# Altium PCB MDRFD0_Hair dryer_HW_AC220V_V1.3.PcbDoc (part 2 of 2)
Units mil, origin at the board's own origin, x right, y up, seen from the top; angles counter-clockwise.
Board outline 2501.37 x 2501.36 mil, 2 copper layers (Top Layer, Bottom Layer), stack 65.792 mil thick; 130 components, 77 nets, 332 pads, 233 vias.
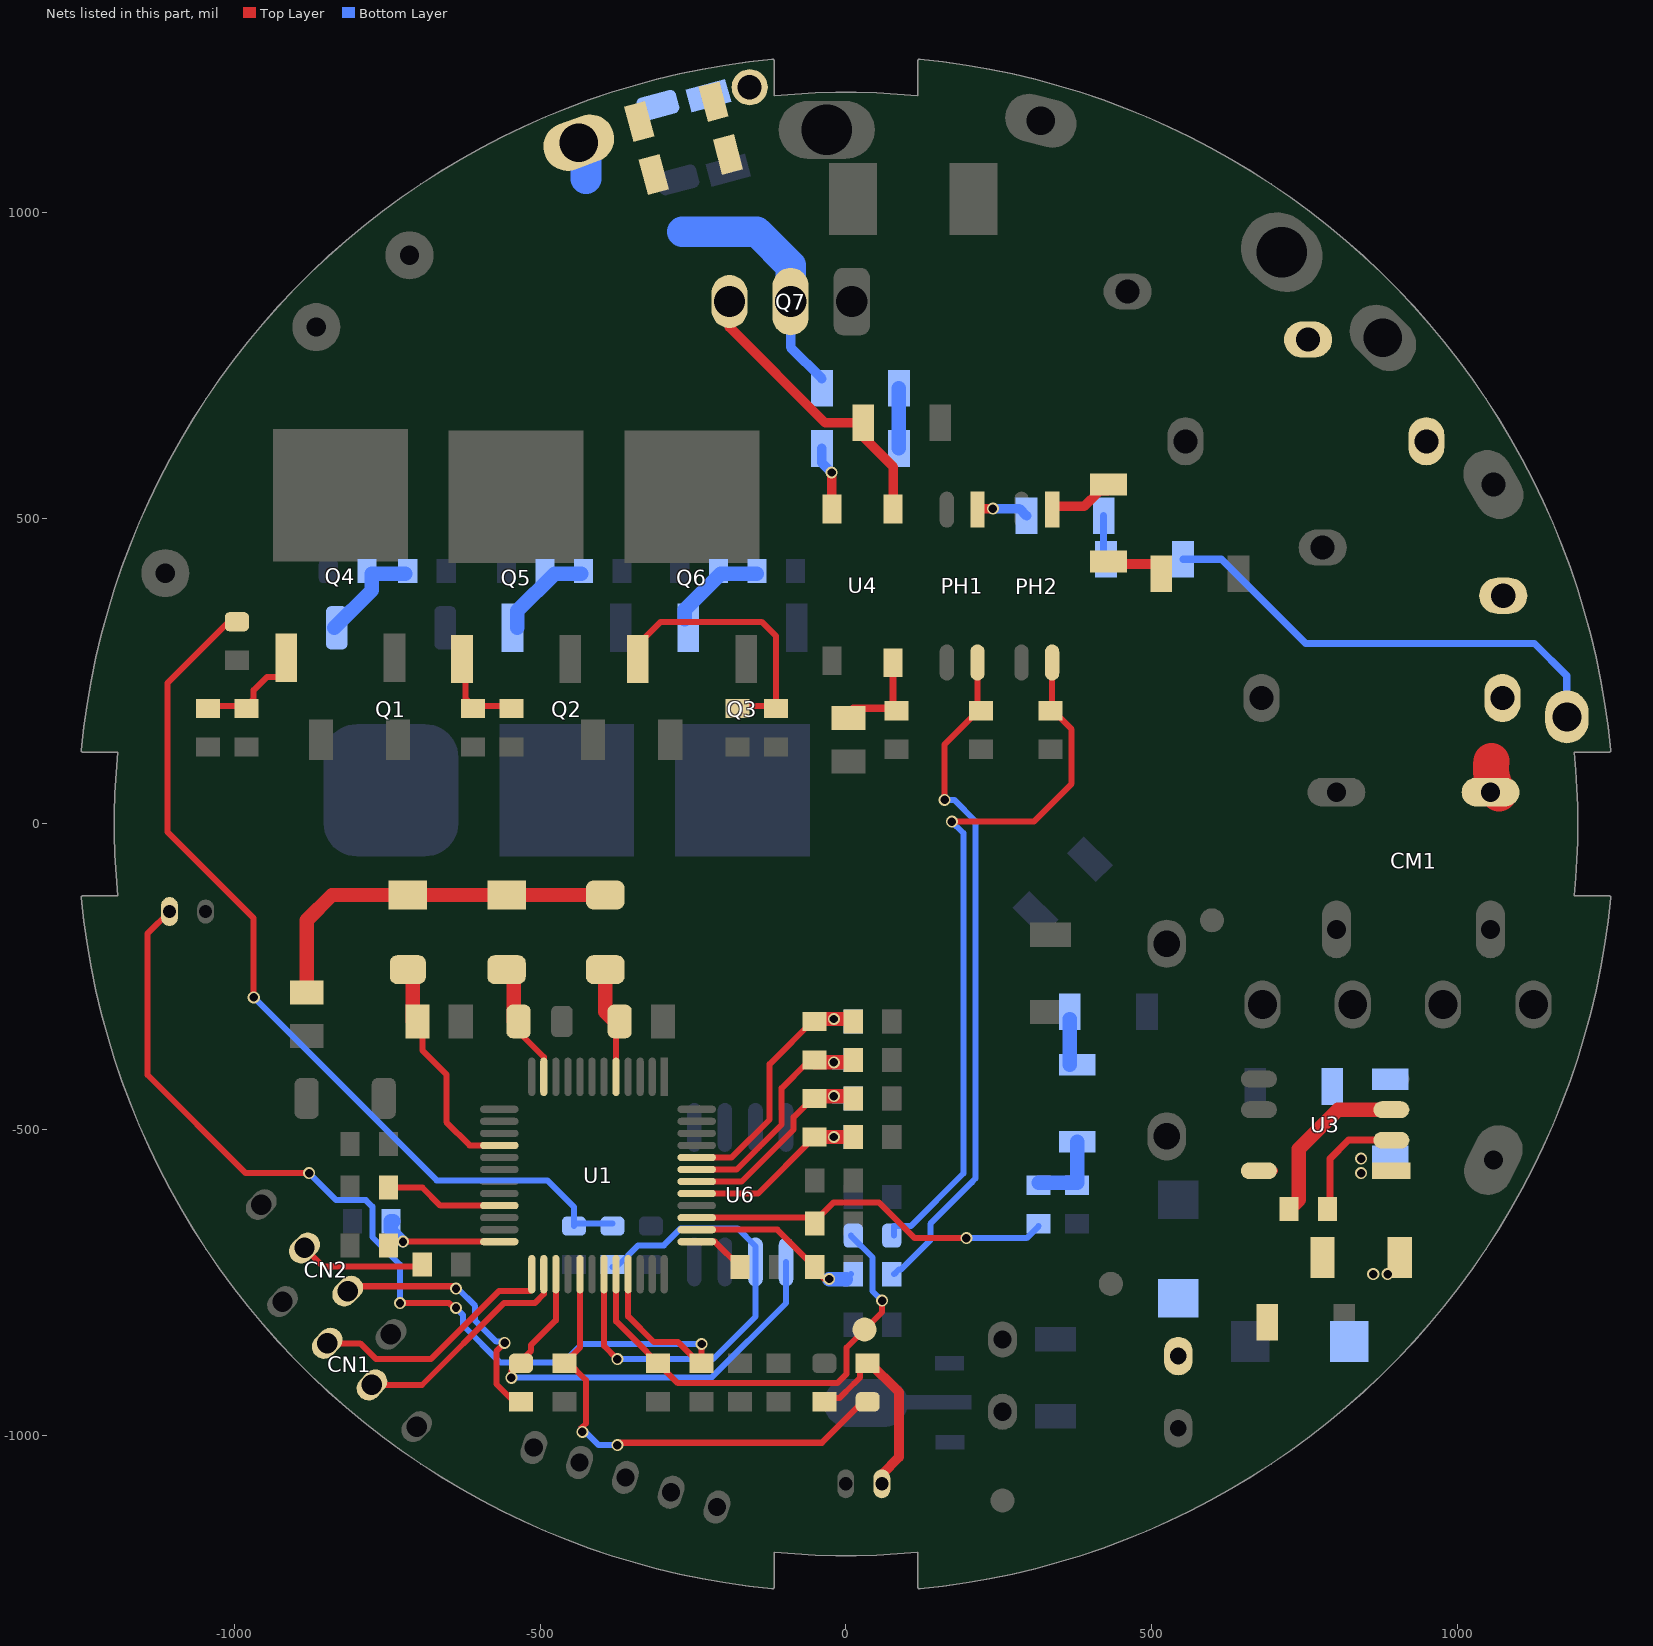
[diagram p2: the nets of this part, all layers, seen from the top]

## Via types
v1: diameter 19.68, hole 13.78, Top Layer to Bottom Layer, tented both sides, 233 vias

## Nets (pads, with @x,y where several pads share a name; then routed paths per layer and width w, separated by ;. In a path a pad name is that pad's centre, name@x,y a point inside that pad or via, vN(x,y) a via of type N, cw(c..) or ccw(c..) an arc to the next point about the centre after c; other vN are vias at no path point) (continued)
NetC5_2: C5.2 C6.1 D4.2 L2.1 R7.1 U3.3 U3.8 | length 306.3
  Top Layer w11.81: U3.8@677.64,-566.93 U3.8@700.79,-566.93
  Top Layer w23.62: C6.1@724.41,-629.92 740.16,-614.17 740.16,-531.5 804.53,-467.13 U3.3@891.73,-467.13
NetC6_2: C6.2 U3.2 | length 201.5
  Top Layer w11.81: C6.2@791.34,-629.92 791.34,-547.24 821.65,-516.93 U3.2@897.64,-516.93
NetC11_1: C11.1 C26.1 pad.2 R41.1 R42.1
NetC29_2: C29.2 R36.1 U1.24 | length 230.7
  Top Layer w9.84: C29.2@-748.03,-688.98 -742.13,-683.07 v1(-724.41,-683.07) U1.24@-566.93,-683.07
  Bottom Layer w19.68: R36.1@-744.09,-663.39 v1(-724.41,-683.07)
  Bottom Layer w23.62: R36.1@-744.09,-663.39 R36.1@-744.09,-653.54 ; R36.1@-744.09,-649.61 R36.1@-744.09,-653.54 ; R36.1@-740.16,-649.61 R36.1@-744.09,-653.54
NetC32_1: C32.1 U1.21 | length 193.3
  Top Layer w9.84: C32.1@-748.03,-594.49 -692.91,-594.49 -663.39,-624.02 U1.21@-566.93,-624.02
NetCM1_1: CM1.1 CX1.2 CX2.2 MOV1.2 THR1.2 | length 111.6
  Top Layer w59.06: 1055.74,103.06 ccw(c1125.8,91.05) 1067.77,50.01 cw(c1125.8,91.05) 1055.74,103.06
NetD5_1: D5.1 D6.1 D7.1 R44.2 | length 615.5
  Top Layer w23.62: R44.2@-881.89,-267.72 -881.89,-157.48 -840.55,-116.14 D7.1@-393.7,-116.14
NetNTC1_2: NTC1.2 R43.2 R46.1 | length 1488.7
  Top Layer w9.84: NTC1.2@-996.06,334.65 -1005.44,334.65 -1109.25,230.83 -1109.25,-13.31 -968.5,-154.06 v1(-968.5,-283.46)
  Bottom Layer w9.84: v1(-968.5,-283.46) -669.29,-582.68 -488.38,-582.68 -444.88,-626.18 R43.2@-444.88,-653.54 ; R43.2@-444.88,-657.48 R43.2@-444.88,-653.54 ; R46.1@-381.89,-653.54 R43.2@-444.88,-653.54
NetNTC_1: NTC.1 R30.1 R40.1 | length 330.2
  Top Layer w9.84: R40.1@-35.43,-948.82 -25.59,-938.98 -11.04,-938.98 13.08,-914.86 13.25,-914.86 23.07,-905.04 R30.1@23.07,-885.36
  Top Layer w15.75: R30.1@35.43,-877.95 86.61,-929.13 86.61,-1035.43 58.66,-1063.39 NTC.1@58.66,-1079.02
NetPAD6_1: PAD6.1 R4.1 | length 773.8
  Bottom Layer w11.81: R4.1@551.18,433.07 614.17,433.07 751.97,295.28 1125.98,295.28 1178.74,242.52 PAD6.1@1178.74,175.2
NetPAD7_1: PAD7.1 Q7.2 R39.1 R41.2 R42.2 | length 469.2
  Bottom Layer w15.75: Q7.2@-90.55,854.33 -90.55,779.53 R39.1@-39.37,728.35
  Bottom Layer w50: -425.2,1055.12 PAD7.1@-425.2,1118.11 ; -267.72,968.5 -145.67,968.5 -90.55,913.39 Q7.2@-90.55,854.33
NetPH1_1: PH1.1 R22.2 | length 85.9
  Top Layer w15.75: PH1.1@215,514 216.75,515.75 v1(240.16,515.75)
  Bottom Layer w15.75: v1(240.16,515.75) 283.46,515.75 R22.2@295.28,503.94
NetPH1_4: PH1.4 R9.1 R20.1 | length 1114
  Top Layer w9.84: v1(161.42,39.37) 161.42,130.12 220.47,189.17 215,194.65 PH1.4@215,264
  Bottom Layer w9.84: R20.1@78.74,-736.22 86.61,-728.35 90.03,-728.35 137.8,-680.58 137.8,-653.82 205.71,-585.91 205.71,-585.63 211.61,-579.72 211.61,4.92 177.17,39.37 v1(161.42,39.37)
NetPH2_1: PH2.1 R35.2 | length 104.3
  Top Layer w11.81: PH2.1@337,514 PH2.1@342.69,519.68 ; R35.2@413.39,543.31 R35.2@429.13,543.31
  Top Layer w15.75: PH2.1@342.69,519.68 389.76,519.68 R35.2@413.39,543.31
NetPH2_4: PH2.4 R8.1 R24.1 | length 1182.6
  Top Layer w9.84: v1(173.23,3.94) 307.09,3.94 369.09,65.95 369.09,154.72 334.65,189.17 337,191.53 PH2.4@337,264
  Bottom Layer w9.84: R24.1@78.74,-673.23 78.74,-657.48 106.02,-657.48 191.93,-571.57 191.93,-14.76 v1(173.23,3.94)
NetQ1_1: Q1.1 R12.2 R15.2 | length 169
  Bottom Layer w23.62: Q1.1@-836.61,320.87 -775.59,381.89 -775.59,409.45 R15.2@-720.47,409.45
NetQ2_1: Q2.1 R13.2 R16.2 | length 157.2
  Bottom Layer w23.62: Q2.1@-537.4,320.87 -537.4,348.42 -476.38,409.45 R16.2@-433.07,409.45
NetQ3_1: Q3.1 R14.2 R17.2 | length 154.4
  Bottom Layer w23.62: Q3.1@-263.78,334.65 -263.78,350.39 R14.2@-204.72,409.45 ; R14.2@-200.79,409.45 R17.2@-145.67,409.45
NetQ4_1: Q4.1 R18.2 R21.2 | length 145.9
  Top Layer w9.84: R18.2@-1043.31,192.91 -980.32,192.91 -968.5,204.72 -968.5,218.75 -947.1,240.16 Q4.1@-925.2,240.16
NetQ5_1: Q5.1 R6.2 R19.2 | length 147.1
  Top Layer w9.84: Q5.1@-627.95,269.68 -622.05,263.78 -622.05,204.72 -610.24,192.91 R6.2@-547.24,192.91
NetQ6_1: Q6.1 R5.2 R23.2 | length 452.4
  Top Layer w9.84: Q6.1@-340.55,269.68 -340.55,293.31 -303.15,330.71 -137.8,330.71 -114.17,307.09 -114.17,192.91 R5.2@-177.17,192.91
NetQ7_3: Q7.3 R11.2 U4.4 | length 486.4
  Top Layer w15.75: Q7.3@-190.55,854.33 -190.55,812.6 -33.95,656 R11.2@28.01,656 28.01,633.4 77,584.42 U4.4@77,515.03
NetR1_1: R1.1 R2.2
NetR4_2: R4.2 R22.1 | length 72.5
  Bottom Layer w11.81: R22.1@421.26,503.94 421.26,437.01 R4.2@425.2,433.07
NetR10_1: R10.1 R37.1 U4.3 | length 158.9
  Top Layer w11.81: R37.1@3.94,181.1 12.01,189.17 82.68,189.17 77,194.85 U4.3@77,263.65
NetR25_2: R25.2 R28.1 R33.1 | length 129.9
  Bottom Layer w23.62: R33.1@314.96,-586.61 377.95,-586.61 R28.1@377.95,-519.68
NetR27_1: R27.1 R28.2 | length 74.8
  Bottom Layer w23.62: R28.2@366.14,-393.7 R27.1@366.14,-318.9
NetR29_2: R29.2 R35.1 | length 85.3
  Top Layer w11.81: R29.2@500,425.2 R29.2@515.75,409.45
  Top Layer w15.75: R35.1@437.01,425.2 R29.2@500,425.2
NetR38_1: R38.1 R39.2 | length 98.4
  Bottom Layer w23.62: R38.1@86.61,614.17 R39.2@86.61,712.6
NetR38_2: R38.2 U4.6 | length 98.4
  Top Layer w15.75: U4.6@-23,515.03 v1@-23,567.55
  Bottom Layer w15.75: R38.2@-39.37,614.17 -39.37,590.55 v1(-23.62,574.8)
NTC: C22.1 R30.2 U1.29 | length 774.2
  Top Layer w9.84: U1.29@-435.04,-736.22 -435.04,-856.3 -456.69,-877.95 -425.2,-909.45 -425.2,-980.31 v1@-433.07,-988.19 ; v1(-374.02,-1015.75) -370.08,-1011.81 -39.37,-1011.81 R30.2@23.62,-948.82
  Bottom Layer w9.84: v1@-433.07,-988.19 v1@-429.13,-992.13 ; v1(-431.06,-994.13) -426.15,-994.13 -404.53,-1015.75 v1(-374.02,-1015.75)
OP0N: C9.2 C14.1 R31.2 U1.43 | length 390.1
  Top Layer w9.84: U1.43@-244.09,-564.96 -178.85,-564.96 -105.31,-491.42 -105.31,-432.09 -62.99,-389.76 C9.2@-51.18,-389.76 ; C14.1@3.94,-389.76 C14.1@7.87,-385.83
  Top Layer w23.62: C9.2@-51.18,-389.76 v1(-19.69,-389.76) C14.1@3.94,-389.76
  Bottom Layer w9.84: R31.2@3.94,-389.76 R31.2@7.87,-385.83
  Bottom Layer w23.62: v1(-19.69,-389.76) R31.2@3.94,-389.76
OP0P: C9.1 C10.1 R3.2 U1.44 | length 429.6
  Top Layer w9.84: U1.44@-244.09,-545.28 -187.01,-545.28 -125,-483.27 -125,-392.72 C9.1@-51.18,-318.9 ; C10.1@3.94,-318.9 C10.1@7.87,-322.83
  Top Layer w23.62: C9.1@-51.18,-318.9 v1(-19.69,-318.9) C10.1@3.94,-318.9
  Bottom Layer w9.84: R3.2@3.94,-318.9 R3.2@7.87,-322.83
  Bottom Layer w23.62: v1(-19.69,-318.9) R3.2@3.94,-318.9
OP1N: C24.2 C27.1 R34.2 U1.41 | length 317.9
  Top Layer w9.84: U1.41@-244.09,-604.33 -143.98,-604.33 -55.4,-515.75 -51.18,-515.75 C24.2@-47.24,-511.81
  Top Layer w23.62: C24.2@-47.24,-511.81 v1(-19.69,-511.81) C27.1@7.87,-511.81
  Bottom Layer w23.62: v1(-19.69,-511.81) R34.2@7.87,-511.81
OP1P: C24.1 C25.1 R32.2 U1.42 | length 352.5
  Top Layer w9.84: U1.42@-244.09,-584.65 -170.7,-584.65 -85.63,-499.57 -85.63,-479.33 C24.1@-51.18,-444.88 ; C25.1@3.94,-444.88 C25.1@7.87,-448.82
  Top Layer w23.62: C24.1@-51.18,-444.88 v1(-19.69,-444.88) C25.1@3.94,-444.88
  Bottom Layer w9.84: R32.2@3.94,-444.88 R32.2@7.87,-448.82
  Bottom Layer w23.62: v1(-19.69,-444.88) R32.2@3.94,-444.88
OVP: C12.2 R33.2 U1.39 | length 603.6
  Top Layer w9.84: U1.39@-244.09,-643.7 C12.2@-57.09,-643.7 ; C12.2@-55.12,-653.54 -20.67,-619.09 54.31,-619.09 112.39,-677.17 v1(196.85,-677.17)
  Bottom Layer w9.84: v1(196.85,-677.17) 295.28,-677.17 R33.2@314.96,-657.48
RXD: CN2.2 J_RX.1 | length 438.6
  Top Layer w9.84: CN2.2@-814.8,-763.93 -806.78,-755.91 -641.73,-755.91 v1(-637.8,-759.84) ; v1(-558.1,-848.47) -571.85,-862.22 -571.85,-915.7 -538.74,-948.82 J_RX.1@-531.5,-948.82
  Bottom Layer w9.84: v1(-637.8,-759.84) -634.49,-759.84 -606.3,-788.04 -606.3,-812.01 -571.85,-846.46 v1@-558.07,-846.46
SCL: R46.2 U1.31 U6.6 | length 789.6
  Top Layer w9.84: U1.31@-395.67,-736.22 -395.67,-853.35 v1(-374.02,-875)
  Bottom Layer w9.84: R46.2@-381.89,-724.41 -375.21,-724.41 -339.78,-688.98 -298.02,-688.98 -270.34,-661.3 -177.28,-661.3 -148.03,-690.55 U6.6@-148.03,-716.06 -148.03,-805.51 -217.52,-875 v1(-374.02,-875)
SCL-ICE: CN1.2 U1.26 | length 375.1
  Top Layer w9.84: CN1.2@-775.21,-917.34 -693.28,-917.34 -559.4,-783.46 -508.99,-783.46 -494.09,-768.57 U1.26@-494.09,-736.22
SDA: J_RX.2 U1.27 U6.5 | length 766.6
  Top Layer w9.84: v1(-547.24,-905.51) -547.24,-893.7 -514.76,-861.22 -514.76,-851.87 -474.41,-811.52 U1.27@-474.41,-736.22
  Bottom Layer w9.84: v1(-547.24,-905.51) -220.19,-905.51 -98.03,-783.35 U6.5@-98.03,-716.06
SDA-ICE: CN1.3 U1.25 | length 387.7
  Top Layer w9.84: CN1.3@-848.35,-849.14 -794.38,-849.14 -768.86,-874.66 -678.44,-874.66 -567.56,-763.78 U1.25@-517.14,-763.78
SPEED_ZC: C4.2 R20.2 U1.38 | length 287
  Top Layer w9.84: U1.38@-244.09,-663.39 -112.21,-663.39 C4.2@-55.12,-720.47 ; C4.2@-55.12,-724.41 -35.43,-744.09 v1(-27.56,-744.09)
  Bottom Layer w9.84: R20.2@0,-744.09 R20.2@7.87,-736.22
  Bottom Layer w23.62: v1(-27.56,-744.09) R20.2@0,-744.09
SW_HEAT: C20.1 HEAT_SW.1 U1.33 | length 1705.2
  Top Layer w9.84: HEAT_SW.1@-1106.26,-143.19 -1142.02,-178.95 -1142.02,-410.41 -981.56,-570.87 v1@-881.89,-570.87 ; v1(-729.33,-783.46) -648.97,-783.46 -641.1,-791.34 v1(-637.8,-791.34) ; U1.33@-356.3,-736.22 -356.3,-805.12 -313.98,-847.44 -274.61,-847.44 -244.09,-877.95 -236.22,-870.08 v1(-236.22,-850.39)
  Bottom Layer w9.84: v1(-877.95,-570.87) -833.66,-615.16 -785.22,-615.16 -774.61,-625.77 -774.61,-675.41 -729.33,-720.68 v1(-729.33,-783.46) ; v1@-634.84,-794.29 -625.98,-803.15 -625.98,-820.16 -565.24,-880.91 -462.6,-880.91 -432.09,-850.39 v1(-236.22,-850.39)
TXD: CN2.3 J_TX.1 | length 206.7
  Top Layer w9.84: CN2.3@-885.52,-693.22 -854.82,-723.92 -696.36,-723.92 J_TX.1@-692.91,-720.47
V18: C15.1 U1.37 | length 88
  Top Layer w9.84: U1.37@-244.09,-683.07 -214.57,-683.07 C15.1@-173.23,-724.41
VBU: C16.1 D5.2 U1.16 | length 377.9
  Top Layer w9.84: C16.1@-708.66,-322.83 -692.91,-338.58 -692.91,-370.08 -653.54,-409.45 -653.54,-487.64 -615.59,-525.59 U1.16@-566.93,-525.59
  Top Layer w23.62: D5.2@-716.54,-238.19 -708.66,-246.06 C16.1@-708.66,-322.83
VBV: C19.1 D6.2 U1.11 | length 187.5
  Top Layer w9.84: C19.1@-540.48,-334.65 -494.09,-381.03 U1.11@-494.09,-413.39
  Top Layer w23.62: D6.2@-555.12,-238.19 -543.31,-250 C19.1@-543.31,-322.83
VBW: C21.1 D7.2 U1.5 | length 172.4
  Top Layer w9.84: U1.5@-375.98,-413.39 -375.98,-340.55 C21.1@-370.08,-334.65
  Top Layer w23.62: D7.2@-393.7,-238.19 -393.7,-307.09 C21.1@-377.95,-322.83
VCC: C5.1 D3.2 R2.1 U3.1
  other v1: 862.2,-736.22 885.83,-736.22 842.52,-570.87 842.52,-547.24
ZERO: C3.2 R24.2 U1.32 ZERO.1 | length 773.4
  Top Layer w9.84: U1.32@-375.98,-736.22 -375.98,-813.27 -274.89,-914.37 -14.27,-914.37 0.98,-899.12 0.98,-856.09 ZERO.1@30.3,-826.77 59.06,-798.02 v1(59.06,-779.53)
  Bottom Layer w9.84: R24.2@7.87,-673.23 43.31,-708.66 43.31,-763.78 v1(59.06,-779.53)
pads on no net: U1. U1.1 U1.2 U1.6 U1.7 U1.8 U1.12 U1.13 U1.17 U1.18 U1.19 U6.7

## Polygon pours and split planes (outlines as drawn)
MU on Bottom Layer "Top Layer-No Net 1" (solid, pour order 101): -1039.37,370.08 -1011.81,370.08 -909.45,472.44 -700.79,472.44 -677.17,448.82 -677.17,295.28 -669.29,287.4 -641.73,287.4 -633.86,295.28 -633.86,476.38 -716.54,559.06 -716.54,645.67 -1039.37,645.67
AGND on Bottom Layer "Top Layer-No Net 1" (solid, remove dead copper, pour order 117): -1049.21,-124.02 -661.42,-511.81 -897.64,-511.81 -897.64,-377.95 -1070.87,-204.72 -1070.87,-134.84 -1060.04,-124.02
AGND on Bottom Layer "Top Layer-No Net 1" (solid, pour order 88): 59.06,-672.27 59.06,-311.02 -27.56,-311.02 -145.67,-429.13 -476.38,-429.13 -476.38,-672.27
AGND on Bottom Layer "Top Layer-No Net 1" (solid, remove dead copper, pour order 85): 204.72,-602.36 279.53,-677.17 279.53,-1015.75 0,-1295.28 -484.25,-1295.28 -877.95,-901.57 -980.32,-779.53 -1050.21,-676.2 -830.91,-456.89 -803.15,-429.13 -413.39,-429.13 -240.16,-602.36
AGND on Bottom Layer "Top Layer-No Net 1" (solid, remove dead copper, pour order 107): 110.24,15.75 90.55,-3.94 90.55,-102.36 122.05,-133.86 122.05,-204.72 110.24,-216.54 -43.31,-216.54 -271.65,-444.88 -110.24,-444.88 66.93,-267.72 141.73,-267.72 157.48,-251.97 157.48,-62.99 129.92,-35.43 129.92,11.81 125.98,15.75
HV on Bottom Layer "Top Layer-No Net 1" (solid, pour order 104): 476.38,-295.28 476.38,-177.17 330.71,-31.5 330.71,90.55 267.72,153.54 27.56,153.54 -27.56,98.43 -27.56,-31.5 -51.18,-55.12 -807.09,-55.12 -807.09,161.42 -122.05,161.42 0,283.46 342.52,283.46 665.35,-39.37 665.35,-322.83 637.8,-350.39 535.43,-350.39 492.13,-307.09
MW on Bottom Layer "Top Layer-No Net 1" (solid, pour order 103): -370.08,582.68 -259.84,472.44 -137.8,472.44 -98.43,433.07 -98.43,271.65 -110.24,259.84 -78.74,259.84 -51.18,287.4 -51.18,472.44 -141.73,562.99 -141.73,653.54 -370.08,653.54
HV on Bottom Layer "Top Layer-No Net 1" (solid, pour order 64): 598.43,-157.48 712.6,-271.65 712.6,-472.44 708.66,-476.38 649.61,-476.38 476.38,-303.15 476.38,-185.04 503.94,-157.48
MV on Bottom Layer "Top Layer-No Net 1" (solid, pour order 102): -653.54,590.55 -535.43,472.44 -480.32,472.44 -417.32,472.44 -385.83,440.94 -385.83,262.8 -382.87,259.84 -346.46,259.84 -338.58,267.72 -338.58,480.31 -429.13,570.87 -429.13,649.01
MW on Bottom Layer "Top Layer-No Net 1" (solid, pour order 100): -712.6,889.76 -671.37,889.76 cw(c-671.37,580.6) -452.76,799.21 -370.08,716.54 -370.08,625.98 -370.08,582.68 -366.14,578.74 -145.67,578.74 -141.73,582.68 -141.73,653.54 -165.35,677.17 -337.35,849.16 ccw(c-625.47,561.04) -625.47,968.5 -665.35,968.5 -712.6,968.5
MV on Bottom Layer "Top Layer-No Net 1" (solid, pour order 99): -433.07,578.74 -429.13,582.68 -429.13,649.01 -469.41,689.28 -504.25,689.28 -606.97,792.01 ccw(c-671.87,727.12) -671.88,818.9 -905.51,818.9 -905.51,794.6 ccw(c-869.12,794.6) -894.85,768.87 -876.12,750.14 ccw(c-833.02,793.25) -833.02,732.28 -725.36,732.28 cw(c-725.36,682.46) -690.13,717.69 -674.18,701.74 cw(c-724.01,651.91) -653.54,651.91 -653.54,590.55 -641.73,578.74
MU on Bottom Layer "Top Layer-No Net 1" (solid, remove dead copper, pour order 98): -716.54,645.67 -716.54,586.61 -724.41,578.74 -988.19,578.74 -1007.87,559.06 -1015.75,551.18 -1015.75,460.63 -1015.75,393.7 -1019.69,389.76 -1039.37,370.08 -1114.17,370.08 -1137.8,370.08 -1188.98,421.26 -1188.98,562.99 -1106.3,645.67 -716.54,645.67
+12V on Bottom Layer "Top Layer-No Net 1" (solid, pour order 80): 629.92,-795.28 688.98,-795.28 704.72,-811.02 704.72,-960.63 641.73,-1023.62 149.61,-1023.62 145.67,-1019.68 145.67,-996.06 153.54,-988.19 216.54,-988.19 232.28,-972.44 232.28,-937.01 240.16,-929.13 586.61,-929.13 618.11,-897.64 618.11,-807.09
COM on Bottom Layer "Top Layer-No Net 1" (solid, pour order 81): 291.34,-118.11 338.58,-165.35 338.58,-173.23 314.96,-196.85 275.59,-196.85 259.84,-181.1 259.84,-133.86 275.59,-118.11
NetC5_2 on Bottom Layer "Top Layer-No Net 1" (solid, pour order 79): 562.99,-744.09 507.87,-744.09 507.87,-889.76 519.68,-901.57 562.99,-901.57 578.74,-885.83 578.74,-744.09
VCC on Bottom Layer "Top Layer-No Net 1" (solid, pour order 53): 838.58,-519.68 913.39,-519.68 917.32,-523.62 917.32,-566.93 901.57,-582.68 834.65,-582.68 826.77,-574.8 826.77,-531.5 838.58,-519.68
NetR1_1 on Bottom Layer "Top Layer-No Net 1" (solid, pour order 67): 921.26,-397.64 921.26,-440.94 901.57,-460.63 779.53,-460.63 775.59,-456.69 775.59,-397.64
VCC on Bottom Layer "Top Layer-No Net 1" (solid, pour order 68): 870.08,-724.41 803.15,-724.41 787.4,-740.16 787.4,-877.95 791.34,-881.89 854.33,-881.89 889.76,-846.46 901.57,-834.65 901.57,-736.22 901.57,-732.28 893.7,-724.41
+5V on Bottom Layer "Top Layer-No Net 1" (solid, pour order 82): -854.09,-629.92 -799.21,-629.92 -795.28,-633.86 -795.28,-688.98
AGND on Bottom Layer "Top Layer-No Net 1" (solid, pour order 86): 539.37,-472.44 559.06,-492.13 559.06,-566.93 618.11,-625.98 618.11,-633.86 566.93,-685.04 523.62,-685.04 464.57,-744.09 464.57,-838.58 381.89,-921.26 280.53,-921.26 232.04,-872.76 232.04,-827.2 255.9,-803.33 278.87,-676.51 295.28,-696.85 338.58,-696.85 346.46,-688.98 346.46,-641.73 354.33,-633.86 409.45,-633.86 417.32,-625.98 417.32,-547.24 492.13,-472.44
+5V on Bottom Layer "Top Layer-No Net 1" (solid, pour order 83): 74.8,-803.15 74.8,-807.09 90.55,-807.09 125.98,-775.59 137.8,-763.78 137.8,-787.4 196.85,-846.46 196.85,-893.7 192.91,-897.64 86.61,-897.64 59.06,-870.08 27.56,-870.08 59.06,-842.52 78.74,-822.83
NetCM1_1 on Bottom Layer "Top Layer-No Net 1" (solid, pour order 91): 779.53,822.83 795.28,807.09 795.28,759.84 885.83,669.29 956.69,669.29 976.38,649.61 976.38,523.62 1110.24,389.76 1110.24,358.27 1102.36,350.39 1055.12,350.39 716.54,688.98 716.54,811.02 728.35,822.83
AGND on Bottom Layer "Top Layer-No Net 1" (solid, remove dead copper, pour order 96): 492.13,-472.44 539.37,-472.44 559.06,-492.13 559.06,-555.12 610.24,-606.3 956.69,-606.3 1019.68,-543.31 1090.55,-267.72 1106.3,-251.97 1129.92,-251.97 1145.67,-251.97 1212.6,-318.9 1212.6,-523.62 1051.18,-685.04 523.62,-685.04 484.25,-645.67 484.25,-480.31 492.13,-472.44
COM on Bottom Layer "Top Layer-No Net 1" (solid, pour order 70): -192.91,-196.85 110.24,-196.85 110.24,-137.8 78.74,-106.3 -228.35,-106.3 -240.16,-118.11 -240.16,-149.61
AGND on Top Layer "Top Layer-No Net 1" (solid, remove dead copper, pour order 84): -956.69,-574.8 -771.65,-574.8 -539.37,-610.24 -444.88,-515.75 -322.83,-515.75 -110.24,-303.15 118.11,-303.15 118.11,-551.18 137.8,-570.87 228.35,-570.87 263.78,-606.3 263.78,-897.64 216.54,-944.88 216.54,-1078.74 0,-1295.28 -484.25,-1295.28 -877.95,-901.57 -1050.74,-668.85
AGND on Top Layer "Top Layer-No Net 1" (solid, pour order 87): 232.28,-795.51 251.73,-814.96 275.59,-814.96 283.46,-807.09 283.46,-614.17 330.71,-566.93 425.2,-566.93 460.63,-531.5 555.12,-531.5 555.12,-555.12 515.75,-594.49 515.75,-787.4 397.64,-905.51 220.47,-905.51 200.79,-885.83 200.79,-814.96 220.47,-795.28
AGND on Top Layer "Top Layer-No Net 1" (solid, remove dead copper, pour order 111): -901.57,-421.26 -897.64,-417.32 -874.02,-417.32 -822.83,-366.14 -807.09,-366.14 -791.34,-381.89 -791.34,-401.57 -814.96,-425.2 -814.96,-480.32 -795.28,-500 -795.28,-543.31 -795.28,-555.12 -773.62,-574.8 -784.4,-586.61 -858.27,-586.61 -858.27,-555.12 -901.57,-511.81
+12V on Top Layer "Top Layer-No Net 1" (solid, remove dead copper, pour order 109): -795.28,-484.25 -795.28,-437.01 -771.65,-413.39 -728.35,-413.39 -720.47,-421.26 -720.47,-480.32 -665.35,-535.43 -665.35,-543.31 -775.59,-543.31 -783.46,-535.43 -783.46,-496.06
+12V on Top Layer "Top Layer-No Net 1" (solid, pour order 55): -925.2,-346.46 -905.51,-326.77 -862.2,-326.77 -854.33,-334.65 -854.33,-377.95 -881.89,-405.51 -913.39,-405.51 -925.2,-393.7
I_V on Top Layer "Top Layer-No Net 1" (solid, pour order 60): -401.57,318.9 -381.89,299.21 -381.89,106.3 -425.2,62.99 -523.62,62.99 -566.93,106.3 -566.93,137.8 -519.69,137.8 -507.87,149.61 -507.87,212.6 -543.31,248.03 -543.31,307.09 -531.5,318.9
AGND on Top Layer "Top Layer-No Net 1" (solid, pour order 78): 227.36,-287.4 395.67,-287.4 555.12,-446.85 555.12,-539.37 535.43,-559.06 232.28,-559.06 216.54,-543.31 216.54,-298.23
COM on Top Layer "Top Layer-No Net 1" (solid, pour order 66): -728.35,212.6 -767.72,173.23 -767.72,19.68 -728.35,-19.68 -346.46,-19.68 -169.29,-196.85 -157.48,-196.85 -141.73,-181.1 -141.73,-169.29 -350.39,39.37 -539.37,39.37 -574.8,74.8 -622.05,74.8 -641.73,94.49 -641.73,204.72 -649.61,212.6
MV on Top Layer "Top Layer-No Net 1" (solid, pour order 71): -857.59,822.16 -854.33,818.9 -673.51,818.9 cw(c-673.51,723.18) -605.82,790.86 -561.81,746.85 -534.25,746.85 -429.13,641.73 -429.13,393.7 -433.07,389.76 -649.61,389.76 -653.54,393.7 -653.54,654.22 ccw(c-718.44,654.22) -672.55,700.11 -691.28,718.84 ccw(c-723.73,686.39) -723.73,732.28 -830.71,732.28 cw(c-830.71,798.82) -877.75,751.77 -890.92,764.93 cw(c-855.68,800.17) -905.51,800.17 -905.51,814.96
MU on Top Layer "Top Layer-No Net 1" (solid, remove dead copper, pour order 73): -716.54,645.67 -1074.8,645.67 -1216.54,503.94 -1090.55,377.95 -1078.74,389.76 -724.41,389.76 -716.54,397.64
MW on Top Layer "Top Layer-No Net 1" (solid, pour order 69): -712.6,968.5 -627.1,968.5 cw(c-627.1,557.1) -336.19,848.01 -141.73,653.54 -141.73,397.64 -149.61,389.76 -362.2,389.76 -370.08,397.64 -370.08,716.54 -448.82,795.28 -451.13,797.59 ccw(c-673.66,575.06) -673.66,889.76 -712.6,889.76
CS on Top Layer "Top Layer-No Net 1" (solid, pour order 59): 866.14,-393.7 972.44,-393.7 996.06,-417.32 996.06,-787.4 913.39,-870.08 791.34,-870.08 779.53,-858.27 779.53,-783.46 799.21,-763.78 921.26,-763.78 948.82,-736.22 948.82,-452.76 937.01,-440.94 866.14,-440.94 854.33,-429.13 854.33,-405.51
HV on Top Layer "Top Layer-No Net 1" (solid, pour order 62): 507.87,-157.48 598.43,-157.48 712.6,-271.65 712.6,-413.39 712.6,-472.44 708.66,-476.38 649.61,-476.38 637.8,-464.57 637.8,-370.08 488.19,-220.47 488.19,-173.23 503.94,-157.48
VCC on Top Layer "Top Layer-No Net 1" (solid, pour order 57): 834.65,-535.43 850.39,-535.43 866.14,-551.18 933.07,-551.18 937.01,-555.12 937.01,-728.35 917.32,-748.03 858.27,-748.03 850.39,-740.16 850.39,-720.47 885.83,-685.04 885.83,-606.3 870.08,-590.55 838.58,-590.55 830.71,-582.68 830.71,-539.37
ACN on Top Layer "Top Layer-No Net 1" (solid, remove dead copper, pour order 90): 421.26,862.2 421.26,885.83 511.81,976.38 539.37,1003.94 696.85,1003.94 783.46,1003.94 1106.3,681.1 1110.24,677.17 1110.24,519.68 1082.68,492.13 1082.68,496.06 1007.87,570.87 1007.87,637.8 956.69,688.98 905.51,740.16 885.83,740.16 787.4,838.58 755.91,870.08 673.23,870.08 637.8,870.08 606.3,838.58 433.07,838.58 421.26,850.39
NetCM1_1 on Top Layer "Top Layer-No Net 1" (solid, pour order 93): 1074.8,405.51 1031.5,405.51 1000,374.02 1000,43.31 1015.75,27.56 1090.55,27.56 1102.36,39.37 1102.36,322.83 1118.11,338.58 1118.11,393.7 1106.3,405.51
NetBR1_2 on Top Layer "Top Layer-No Net 1" (solid, pour order 94): 791.34,-125.98 830.71,-125.98 858.27,-153.54 858.27,-326.77 850.39,-334.65 811.02,-334.65 799.21,-322.83 799.21,-228.35 779.53,-208.66 775.59,-204.72 775.59,-145.67 775.59,-133.86 783.46,-125.98
ACN1 on Top Layer "Top Layer-No Net 1" (solid, pour order 95): 1043.31,-125.98 976.38,-125.98 944.88,-157.48 944.88,-318.9 960.63,-334.65 996.06,-334.65 1007.87,-322.83 1007.87,-275.59 1070.87,-212.6 1078.74,-204.72 1078.74,-149.61 1078.74,-133.86 1070.87,-125.98
ACL1 on Top Layer "Top Layer-No Net 1" (solid, pour order 92): 303.15,1196.85 264.22,1196.85 ccw(c264.22,1043.71) 155.93,1151.99 ccw(c313.77,994.16) 90.55,994.15 90.55,952.76 90.55,781.44 ccw(c247.24,781.44) 136.44,670.64 188.98,618.11 511.81,618.11 622.05,507.87 622.05,169.29 763.78,27.56 842.52,27.56 850.39,35.43 850.39,433.07 586.61,696.85 288.92,696.85 cw(c288.92,814.56) 205.68,731.33 cw(c303.03,828.68) 165.35,828.68 cw(c284.3,828.68) 200.19,912.79 377.95,1090.55 377.95,1165.35 350.39,1192.91
COM on Top Layer "Top Layer-No Net 1" (solid, pour order 63): -145.67,311.02 -287.4,311.02 -303.15,295.28 -307.09,291.34 -307.09,153.54 -307.09,90.55 -267.72,51.18 -39.37,-177.17 -23.62,-177.17 -11.81,-165.35 -11.81,-66.93 -47.24,-31.5 -165.35,86.61 -192.91,86.61 -200.79,86.61 -216.54,102.36 -216.54,208.66 -208.66,216.54 -196.85,228.35 -145.67,228.35 -137.8,236.22 -137.8,240.16 -137.8,303.15
I_U on Top Layer "Top Layer-No Net 1" (solid, pour order 58): -940.94,212.6 -893.7,212.6 -854.33,251.97 -854.33,311.02 -846.46,318.9 -728.35,318.9 -720.47,311.02 -720.47,232.28 -795.28,157.48 -826.77,157.48 -834.65,149.61 -834.65,3.94 -854.33,-15.75 -877.95,-15.75 -1000,106.3 -1000,137.8 -952.76,137.8 -940.94,149.61
COM on Top Layer "Top Layer-No Net 1" (solid, pour order 72): 27.56,-181.1 27.56,-55.12 62.99,-19.68 346.46,-19.68 374.02,-47.24 374.02,-196.85 358.27,-212.6 137.8,-212.6 114.17,-188.98 35.43,-188.98 27.56,-181.1
NetC5_2 on Top Layer "Top Layer-No Net 1" (solid, pour order 61): 688.98,-555.12 594.49,-555.12 543.31,-606.3 543.31,-763.78 570.87,-791.34 570.87,-814.96 559.06,-826.77 539.37,-826.77 515.75,-850.39 515.75,-885.83 535.43,-905.51 653.54,-905.51 712.6,-846.46 712.6,-783.46 704.72,-775.59 665.35,-775.59 618.11,-728.35 618.11,-645.67 688.98,-574.8
NetC5_2 on Top Layer "Top Layer-No Net 1" (solid, remove dead copper, pour order 54): 803.15,-744.09 704.72,-744.09 677.17,-716.54 677.17,-606.3 685.04,-598.43 685.04,-559.06 688.98,-555.12 708.66,-555.12 716.54,-562.99 716.54,-622.05 767.72,-673.23 807.09,-673.23 807.09,-740.16

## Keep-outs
Keep-Out Layer:
  circle w5: c-507.87,746.85 r68.9
  circle w5: c-1055.12,-374.41 r68.9
  circle w5: c294.49,826.77 r68.9
  lines w5: -1248.17,-120.1 ccw(c0,0) -120.1,-1248.17 ; -1248.17,120.1 cw(c0,0) -120.1,1248.17 ; -1247.13,-120 -1188,-120 cw(c0,0) -1188,120 -1247.13,120 ; -120,-1247.13 -120,-1188 ccw(c0,0) 120,-1188 120,-1247.13 ; -120,1247.14 -120,1188 cw(c0,0) 120,1188 120,1247.14 ; 120.1,-1248.17 ccw(c0,0) 1248.17,-120.1 ; 120.1,1248.17 cw(c0,0) 1248.17,120.1 ; 1247.13,-120 1188,-120 ccw(c0,0) 1188,120 1247.13,120

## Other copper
Top Layer:
  region net NetC11_1: -219.58,1070 -250.73,1182.15 cw(c-234.62,1186.62) -246.44,1198.44 cw(c-155.24,1107.24) -155.23,1236.22 cw(c-155.23,1213.14) -138.91,1229.46 -129.69,1220.24 cw(c-138.62,1211.3) -125.98,1211.3 -125.98,1198.48 cw(c-139.42,1198.48) -129.92,1188.98 -138.98,1179.91 ccw(c-99.75,1140.68) -155.23,1140.68 -155.23,1099.65 cw(c-190.78,1099.65) -165.65,1074.51 -169.29,1070.87 -205.52,1061.81 cw(c-208.34,1073.12)
  region net ACL: -77.11,1014.12 -39.37,976.38 cw(c-74.8,940.95) -25.2,948.03 -19.69,909.45 -19.69,854.33 39.37,854.33 39.37,909.45 51.18,960.63 51.18,1136.16 ccw(c9.23,1136.17) 38.89,1165.83 ccw(c2.03,1128.98) 2.03,1181.1 -69.24,1181.1 ccw(c-69.24,1139.15) -98.9,1168.81 ccw(c-71.54,1141.45) -110.24,1141.45 -110.24,1094.09 ccw(c2.87,1094.09)
  region net NetPAD7_1: -62.99,858.27 -62.99,902.25 ccw(c-118.36,902.26) -79.22,941.42 -113.22,975.42 ccw(c-191.54,897.11) -191.56,1007.87 -219.52,1007.87 cw(c-219.52,1115.23) -291.34,1035.43 -330.71,1181.1 -409.45,1165.35 -478.7,1139.84 -482.44,1137.12 ccw(c-463,1110.38) -496.06,1110.38 -496.06,1101.69 ccw(c-469.18,1101.69) -488.19,1082.68 -386.11,980.59 ccw(c-309.39,1057.31) -309.39,948.82 -175.42,948.82 cw(c-175.41,924.56) -158.24,941.7 -131.55,915.02 cw(c-163.96,882.58) -118.11,882.57 -118.11,858.27
Bottom Layer:
  region net +12V: -521.03,-1097.08 -510.57,-1086.61 -515.39,-1081.79 -525.86,-1092.25
  region net NetC11_1: -155.22,1236.12 ccw(c-145.7,786.66) -269.23,1218.91 -288.38,1213.44 ccw(c-216.36,961.34) -331.02,1197.13 ccw(c-319.02,1172.46) -346.46,1172.46 ccw(c-319.81,1172.46) -338.65,1153.61 ccw(c-323.62,1168.64) -319.67,1147.76 -214.38,1167.68 cw(c-155.19,854.86) -155.17,1173.23 ccw(c-155.17,1196.17) -138.95,1179.95 -132.71,1186.19 ccw(c-148.93,1202.42) -125.98,1202.42 -125.98,1211.3 ccw(c-138.62,1211.3) -129.69,1220.24 -139.09,1229.64 ccw(c-154.74,1213.99)
  region net ACL: -307.09,1043.31 -295.28,1027.56 cw(c-128.47,304.74) -220.33,1040.85 ccw(c-244.09,1231.23) -197.56,1045.1 -173.41,1051.13 cw(c-141.07,921.78) -141.06,1055.12 cw(c-141.05,1004.48) -105.25,1040.28 -37.94,972.98 cw(c-64.72,946.2) -27.44,952.85 -19.69,909.45 -19.69,854.33 39.37,854.33 39.37,909.45 51.18,964.57 51.18,1110.24 51.18,1137.51 ccw(c12.5,1137.52) 39.85,1164.88 ccw(c0.68,1125.72) 0.68,1181.1 -67.6,1181.1 ccw(c-67.61,1135.22) -100.06,1167.66 -143.09,1124.63 cw(c-166.52,1148.06) -166.53,1114.92 -295.43,1080.08 ccw(c-290.05,1060.17) -310.05,1055.17
  region net NetPAD7_1: -480.42,1074.91 -372.19,966.68 ccw(c-319.57,1019.29) -319.57,944.88 -232.28,944.88 -232.28,992.13 -295.28,992.13 cw(c-295.28,1074.8) -377.95,1074.8 -377.95,1124.29 ccw(c-410.78,1124.3) -394.62,1152.87 -399.74,1155.77 ccw(c-420.94,1118.31) -437.64,1157.98 -472.85,1143.15 ccw(c-458.86,1109.92) -494.92,1109.91 ccw(c-445.42,1109.91)

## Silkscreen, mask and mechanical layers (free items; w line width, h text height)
Top Overlay:
  circle w59.06: c-1055.12,-374.41 r98.43
  circle w59.06: c294.49,826.77 r98.43
  lines w19.68: 523.62,-712.6 523.62,-562.99 ; 523.62,-460.63 523.62,-251.97 ; 523.62,-141.73 523.62,0
Bottom Overlay:
  circle w55.12: c-1112.99,410.23 r66.93
  circle w55.12: c-866.14,812.6 r66.93
  circle w59.06: c-1055.12,-374.41 r98.43
  circle w55.12: c-713.78,929.92 r66.93
  circle w59.06: c294.49,826.77 r98.43
  lines w10: -473.3,1151.94 ccw(c-456.74,1106.44) -438.6,1061.54 -403.81,1075.88 ccw(c-420.38,1121.38) -438.52,1166.28 -473.3,1151.94 ; -62.99,1078.35 cw(c-62.99,1135.04) -62.99,1191.73 -0.39,1191.73 cw(c-0.39,1135.04) -0.39,1078.35 -62.99,1078.35 ; 287.51,1108.62 cw(c300.04,1155.39) 312.58,1202.17 349.61,1191.73 cw(c337.07,1144.96) 324.54,1098.18 287.51,1108.62 ; 655.12,895.67 cw(c705.45,941.38) 751.48,991.42 770.08,974.8 cw(c719.75,929.09) 673.71,879.05 655.12,895.67 ; 830,768.59 cw(c866.98,805.57) 903.97,842.55 926.33,820.82 cw(c889.35,783.83) 852.36,746.85 830,768.59 ; 1007.09,-548.03 ccw(c1049.55,-568.74) 1092.01,-589.45 1110.54,-551.87 ccw(c1068.08,-531.16) 1025.61,-510.45 1007.09,-548.03 ; 1007.07,547.87 cw(c1049.01,572.09) 1090.95,596.3 1110.63,562.2 cw(c1068.69,537.99) 1026.75,513.78 1007.07,547.87 ; 1134.25,167.32 ccw(c1178.54,167.32) 1222.83,167.32 1222.83,183.46 ccw(c1178.54,183.46) 1134.25,183.46 1134.25,167.32
  text "ACL" at 141.73,1031.5 h47.24
  text "O2_L" at 405.51,1031.5 h47.24
  text "HEAT_L" at -346.46,1000 h47.24
  text "ACN" at 625.98,913.39 h47.24
  text "W" at -559.06,814.96 h60
  text "HEAT_N" at 850.39,688.98 h47.24
  text "V" at -976,661 h60
  text "U" at -1048,515 h60
  text "O2_N" at 1007.87,476.38 h47.24
  text "HIGH" at 1171.26,109.05 h47.24 r90
  text "GND" at -988.19,-200.79 h27.56
  text "EARTH" at 1082.68,-248.03 h47.24 r90
  text "GND" at -952.76,-578.74 h27.56 r45
  text "TX" at -893.7,-653.54 h27.56 r45
  text "RX" at -822.83,-724.41 h27.56 r45
  text "+5v" at -724.41,-775.59 h27.56 r45
  text "GND" at -850.39,-795.28 h27.56 r45
  text "SDA" at -783.46,-862.2 h27.56 r45
  text "SCL" at -712.6,-933.07 h27.56 r45
  text "+5v" at -625.98,-988.19 h27.56 r45
  text "22-MDRFD0-00" at 531.5,-1086.61 h27.56
  text "20221219" at 421.26,-1141.73 h27.56
  text "GND" at 21.65,-1144.68 h27.56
